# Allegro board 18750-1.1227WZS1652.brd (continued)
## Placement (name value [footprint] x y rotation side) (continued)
C7608  SCD22U10V2KX-1GP  [C402H22]  125.61 142.98 225 bottom
C7610  SC4D7U6D3V2MX-1-GP  [C402H22]  132.44 151.11 45 bottom
C7611  SC4D7U6D3V3KX-GP  [C603H36]  121.02 142.13 180 bottom
C7612  SC1U6D3V1MX-GP  [C0201H14]  134.99 150.82 315 bottom
C7613  SC4D7U6D3V3KX-GP  [C603H36]  118.64 142.16 180 bottom
C7614  SC1U6D3V1MX-GP  [C0201H14]  127.43 147.75 270 top
C7615  SC4D7U6D3V3KX-DLGP  [C603H36]  124.15 131.22 315 top
C7616  SCD1U25V2KX-GP  [C402H22]  127.16 132.91 225 top
C7620  SC4D7U6D3V3KX-GP  [C603H36]  129.49 148.77 45 bottom
C7621  SC4D7U6D3V3KX-GP  [C603H36]  127.94 148.62 270 top
C7622  SC1U6D3V1MX-GP  [C0201H14]  129.72 150.32 315 bottom
C7623  SC10U6D3V3MX-GP  [C603H38]  122.24 144.17 0 bottom
C7624  SC4D7U6D3V3KX-DLGP  [C603H36]  123.32 132.05 315 top
C7625  SC10U6D3V3MX-GP  [C603H38]  131.45 150.72 45 bottom
C7626  SC22U6D3V3MX-1-GP  [C603H40]  119.83 142.13 180 bottom
C7627  SC10U6D3V3MX-GP  [C603H38]  130.2 150.39 180 top
C7628  SC22U6D3V3MX-1-GP  [C603H40]  129.04 150.39 180 top
C7629  SC10U6D3V3MX-GP  [C603H38]  130.12 135.75 135 top
C7630  SC1U6D3V1MX-GP  [C0201H14]  130.1 149.94 315 bottom
C7631  SC1U6D3V1MX-GP  [C0201H14]  130.48 149.56 315 bottom
C7632  SCD1U16V2KX-3GP  [C402H22]  129.14 137.45 315 top
C7633  SC1U6D3V1MX-GP  [C0201H14]  132.21 150.47 180 top
C7634  SC4D7U6D3V3KX-DLGP  [C603H36]  131.37 150.5 180 top
C7744  SC10U6D3V3MX-DL-GP  [C603H36]  143.71 102.88 270 top
C7745  SC10U6D3V3MX-DL-GP  [C603H36]  127.54 118.92 135 bottom
C7746  SC10U6D3V3MX-DL-GP  [C603H36]  126.7 119.76 135 bottom
C7801  SCD1U16V2KX-3GP  [C402H22]  136.99 128.28 225 top
C7802  SCD1U16V2KX-3GP  [C402H22]  138.71 130.02 225 top
C7805  SCD1U16V2KX-3GP  [C402H22]  136.42 132.14 315 top
C7807  SC1U6D3V1MX-GP  [C0201H14]  166.88 130.1 180 top
C7808  SCD1U16V2KX-3GP  [C402H22]  136.18 132.99 315 top
C7809  SCD1U16V2KX-3GP  [C402H22]  137.54 128.84 225 top
C7810  SC1U50V3KX-GP  [C603H32]  127.38 146.91 315 bottom
C7811  SC1U50V3KX-GP  [C603H32]  128.22 146.08 315 bottom
C7812  SC1U50V3KX-GP  [C603H32]  164.8 142.83 270 top
C7813  SC4D7U6D3V3KX-GP  [C603H36]  127.38 143.56 135 bottom
C7814  SC4D7U6D3V3KX-GP  [C603H36]  129.06 145.24 315 bottom
C7817  SC10U6D3V3MX-DL-GP  [C603H36]  126.55 144.4 135 bottom
C7818  SC22U6D3V3MX-1-GP  [C603H40]  134.03 133.15 315 top
C7819  SC10U6D3V3MX-GP  [C603H38]  152.4 149.15 0 top
C7820  SC22U6D3V3MX-1-GP  [C603H40]  155.4 151.74 180 top
C7821  SC22U6D3V3MX-1-GP  [C603H40]  156.72 151.74 180 top
C7822  SC22U6D3V3MX-1-GP  [C603H40]  160.53 151.69 180 top
C7823  SC10U6D3V3MX-GP  [C603H38]  163.2 115.11 0 top
C7824  SC10U6D3V3MX-GP  [C603H38]  154.08 151.74 180 top
C7825  SC1U50V3KX-GP  [C603H32]  164.47 115.11 0 top
C7826  SC1U50V3KX-GP  [C603H32]  165.23 136.7 0 top
C7827  SC1U50V3KX-GP  [C603H32]  154.05 115.11 0 top
C7828  SC1U50V3KX-GP  [C603H32]  156.85 115.11 0 top
C7829  SC10U6D3V3MX-GP  [C603H38]  165.79 130.05 180 top
C7902  SCD1U16V2KX-3GP  [C402H22]  129.64 126.72 315 top
C7905  SCD1U16V2KX-3GP  [C402H22]  132.96 123.97 45 top
C7906  SCD1U16V2KX-3GP  [C402H22]  133.51 124.51 45 top
C7907  SC18P50V2JN-1-GP  [C402H22]  154.34 111.34 180 bottom
C7908  SC18P50V2JN-1-GP  [C402H22]  155.28 108.9 0 bottom
C7934  SC4D7U6D3V3KX-GP  [C603H36]  132.06 127.05 135 top
C7935  SC22U6D3V3MX-1-GP  [C603H40]  131.22 127.89 135 top
C8001  SC4D7U6D3V3KX-GP  [C603H36]  152.79 103.16 90 top
C8002  SC4D7U6D3V3KX-GP  [C603H36]  132.34 131.47 135 top
C8003  SC4D7U6D3V3KX-GP  [C603H36]  164.7 111.71 270 bottom
C8004  SC4D7U6D3V3KX-GP  [C603H36]  150.26 118.15 180 bottom
C8008  SC4D7U6D3V3KX-GP  [C603H36]  127.63 129.62 315 top
C8009  SC4D7U6D3V3KX-GP  [C603H36]  134.7 131.14 315 top
C8010  SC22U6D3V3MX-1-GP  [C603H40]  149.36 111.61 90 top
C8011  SC1U6D3V1MX-GP  [C0201H14]  152.91 105.34 90 top
C8012  SC1U6D3V1MX-GP  [C0201H14]  129.16 133.27 315 top
C8013  SC1U6D3V1MX-GP  [C0201H14]  128.04 132.31 135 top
C8014  SC1U6D3V1MX-GP  [C0201H14]  130.22 134.33 135 top
C8015  SC4D7U6D3V3KX-GP  [C603H36]  132.9 129.57 135 top
C8016  SC4D7U6D3V3KX-GP  [C603H36]  131.02 132.99 315 top
C8017  SC22U6D3V3MX-1-GP  [C603H40]  136.95 130.53 135 top
C8018  SC1U6D3V1MX-GP  [C0201H14]  127.31 131.57 315 top
C8019  SC4D7U6D3V3KX-GP  [C603H36]  143.74 106.99 90 bottom
C8020  SC4D7U6D3V3KX-GP  [C603H36]  150.39 108.23 135 top
C8021  SC4D7U6D3V3KX-GP  [C603H36]  129.31 131.29 135 top
C8022  SC4D7U6D3V3KX-GP  [C603H36]  120.85 125.64 135 bottom
C8023  SC4D7U6D3V3KX-GP  [C603H36]  121.68 124.8 135 bottom
C8024  SC4D7U6D3V3KX-GP  [C603H36]  123.35 123.12 135 bottom
C8025  SC4D7U6D3V3KX-GP  [C603H36]  135.26 128.84 315 top
C8026  SC4D7U6D3V3KX-GP  [C603H36]  130.63 129.8 315 top
C8028  SC1U6D3V1MX-GP  [C0201H14]  135.56 124.28 45 top
C8029  SCD1U16V2KX-3GP  [C402H22]  134.14 123.55 315 top
C8030  SC4D7U6D3V3KX-GP  [C603H36]  122.53 123.98 135 bottom
C8031  SC4D7U6D3V3KX-GP  [C603H36]  152.8 104.35 90 top
C8032  SC4D7U6D3V3KX-GP  [C603H36]  143.71 105.42 270 top
C8034  SCD1U16V2KX-3GP  [C402H22]  162.36 111.94 0 bottom
C8035  SCD1U16V2KX-3GP  [C402H22]  148.92 117.35 270 bottom
C8036  SC1U6D3V1MX-GP  [C0201H14]  136.53 125.15 45 top
C8038  SC10U6D3V3MX-DL-GP  [C603H36]  125.02 121.44 135 bottom
C8039  SC10U6D3V3MX-DL-GP  [C603H36]  124.18 122.28 135 bottom
C8040  SC10U6D3V3MX-DL-GP  [C603H36]  143.71 104.15 270 top
C8041  SC10U6D3V3MX-DL-GP  [C603H36]  119.16 127.3 135 bottom
C8042  SC10U6D3V3MX-DL-GP  [C603H36]  125.86 120.6 135 bottom
C8043  SC10U6D3V3MX-DL-GP  [C603H36]  120.01 126.46 135 bottom
C8047  SC22U6D3V3MX-1-GP  [C603H40]  135.87 126.93 225 top
C8048  SC4D7U6D3V3KX-GP  [C603H36]  138.97 121.51 0 top
C8049  SCD1U16V2KX-3GP  [C402H22]  136.05 124.72 45 top
C8050  SC1U6D3V1MX-GP  [C0201H14]  134.95 125.1 315 top
C8051  SCD1U16V2KX-3GP  [C402H22]  136.88 127.31 225 top
C8101  SC1U6D3V1MX-GP  [C0201H14]  166.75 150.8 270 bottom
C8102  SC1U6D3V1MX-GP  [C0201H14]  158.45 115.09 180 bottom
C8103  SC1U6D3V1MX-GP  [C0201H14]  157.36 129.34 90 bottom
C8104  SC1U6D3V1MX-GP  [C0201H14]  166.5 129.29 270 bottom
C8105  SC1U6D3V1MX-GP  [C0201H14]  166.37 115.88 270 bottom
C8106  SC1U6D3V1MX-GP  [C0201H14]  164.85 136.58 270 bottom
C8107  SC1U6D3V1MX-GP  [C0201H14]  154.31 150.8 90 bottom
C8108  SC1U6D3V1MX-GP  [C0201H14]  157.08 115.88 90 bottom
C8109  SC1U6D3V1MX-GP  [C0201H14]  154.31 137.34 270 top
C8110  SC1U6D3V1MX-GP  [C0201H14]  163.07 129.34 270 bottom
C8111  SC10U6D3V3MX-GP  [C603H38]  158.12 115.11 0 top
C8112  SC10U6D3V3MX-GP  [C603H38]  152.45 118.06 180 top
C8113  SC10U6D3V3MX-GP  [C603H38]  152.83 151.74 180 top
C8114  SC10U6D3V3MX-GP  [C603H38]  163.3 121.97 270 top
C8115  SC1U6D3V1MX-GP  [C0201H14]  155.83 129.34 90 bottom
C8116  SC1U6D3V1MX-GP  [C0201H14]  165.1 150.8 270 bottom
C8117  SC1U6D3V1MX-GP  [C0201H14]  164.72 129.34 270 bottom
C8118  SC1U6D3V1MX-GP  [C0201H14]  157.69 151.03 90 bottom
C8119  SC1U6D3V1MX-GP  [C0201H14]  154.18 129.34 90 bottom
C8120  SC1U6D3V1MX-GP  [C0201H14]  163.2 136.58 270 bottom
C8121  SC1U6D3V1MX-GP  [C0201H14]  155.83 137.34 270 top
C8122  SC1U6D3V1MX-GP  [C0201H14]  166.63 136.58 270 bottom
C8123  SC10U6D3V3MX-GP  [C603H38]  164.57 145.39 270 top
C8124  SC10U6D3V3MX-GP  [C603H38]  163.3 123.14 270 top
C8125  SC10U6D3V3MX-GP  [C603H38]  157.99 151.69 180 top
C8126  SC10U6D3V3MX-GP  [C603H38]  163.96 136.7 0 top
C8127  SC10U6D3V3MX-GP  [C603H38]  160.66 115.11 0 top
C8128  SC10U6D3V3MX-GP  [C603H38]  155.32 115.11 0 top
C8129  SC10U6D3V3MX-GP  [C603H38]  159.39 115.11 0 top
C8130  SC10U6D3V3MX-GP  [C603H38]  164.6 130.05 180 top
C8131  SC1U6D3V1MX-GP  [C0201H14]  155.58 115.88 90 bottom
C8132  SC1U6D3V1MX-GP  [C0201H14]  154.05 115.88 90 bottom
C8136  SC820P50V2KX-1-DL-GP  [C402H22]  164.17 115.12 180 bottom
C8140  SC820P50V2KX-1-DL-GP  [C402H22]  160.81 151.59 270 bottom
C8141  SCD01U50V2KX-1DLGP  [C402H22]  150.12 143.56 90 bottom
C8142  SCD01U50V2KX-1DLGP  [C402H22]  152.28 119.69 270 top
C8143  SC22U6D3V3MX-1-DL-GP  [C603H40]  161.93 115.11 0 top
C8144  SC22U6D3V3MX-1-DL-GP  [C603H40]  165.74 115.11 0 top
C8145  SC22U6D3V3MX-1-DL-GP  [C603H40]  159.26 151.69 180 top
C8146  SC22U6D3V3MX-1-DL-GP  [C603H40]  163.4 130.05 180 top
C8501  SE33U25VM-11-GP  [CT7343H83]  136.15 84.38 180 bottom
C8502  ST22U25VBM-GP  [CT3528H79]  154.64 80.62 90 bottom
C8601  SC1U6D3V1MX-GP  [C0201H14]  167.21 111.46 0 bottom
C8603  SCD1U25V2KX-1-DL-GP  [C402H22]  163.12 111.94 0 bottom
C8605  SC470P50V2KX-3DLGP  [C402H22]  161.19 109.68 90 bottom
C8608  SC470P50V2KX-3DLGP  [C402H22]  161.19 110.49 90 bottom
C8625  SC10U6D3V3MX-GP  [C603H38]  162.92 107.44 180 bottom
C8626  SC10U6D3V3MX-GP  [C603H38]  161.72 107.01 180 bottom
C8627  SC1U6D3V1MX-GP  [C0201H14]  166.55 111.46 0 bottom
C8802  SCD1U16V2KX-L-GP  [C402H22]  97.49 149.86 180 top
C8803  SCD022U16V2KX-3GP  [C402H22]  109.58 150.8 0 top
C8804  SCD01U50V2KX-L-GP  [C402H22]  102.7 142.8 0 bottom
C8805  SCD1U16V2KX-L-GP  [C402H22]  94.03 145.29 270 top
C8806  SCD1U16V2KX-L-GP  [C402H22]  92.03 151.59 90 bottom
C8807  SCD1U16V2KX-L-GP  [C402H22]  101.55 142.01 0 top
C8808  SCD1U16V2KX-L-GP  [C402H22]  108.33 143.69 90 top
C8809  SCD1U16V2KX-L-GP  [C402H22]  100.89 147.06 90 top
C9104  SCD1U16V2KX-3DLGP  [C402H22]  159.54 81.87 0 top
C9106  SC10U6D3V3MX-DL-GP  [C603H36]  164.6 82.86 90 bottom
C9108  SCD1U16V2KX-3DLGP  [C402H22]  164.34 81.46 90 bottom
C9109  SC4D7U6D3V3KX-DLGP  [C603H36]  162.56 79.2 0 bottom
C9112  SCD1U16V2KX-3DLGP  [C402H22]  164.34 78.79 0 bottom
C9113  SCD1U16V2KX-3DLGP  [C402H22]  163.58 78.79 0 bottom
C9201  SC1U6D3V1MX-GP  [C0201H14]  222.56 65.58 180 top
C9202  SC1U6D3V1MX-GP  [C0201H14]  223.07 65.58 180 top
C9203  SCD1U16V2KX-3DLGP  [C402H22]  163.2 68.96 270 top
CPU1  WHISKEY-LAKE-GP  [BGA1528M2446-1H52]  91.24 95.17 270 bottom
D1701  RB520S30-GP  [SOD523AKH26]  146.06 67.37 180 top
D1702  BAW56-9-GP-U  [SOT23-2D4-312H44]  50.93 84.41 180 bottom
D2401  BAT54C-12-GP  [SOT-23-9H44]  21.69 41.23 180 bottom
D2402  L1SS355T1G-GP  [SOD323AKH44]  131.88 39.57 90 bottom
D2403  RB551V30-GP  [SOD323AKH38]  27.59 55.14 0 top
D2404  BAW56-9-GP-U  [SOT23-2D4-312H44]  50.93 81.48 180 bottom
D2501  BAT54C-12-GP  [SOT-23-9H44]  159.47 91.36 180 top
D2502  RB551V30-GP  [SOD323AKH38]  164.97 89.71 0 top
D2503  BAT54A-11-GP  [SOT-23-9H44]  157.94 92 180 bottom
D2601  RB551V30-GP  [SOD323AKH38]  162.87 85.7 90 top
D2703  BAT54C-12-GP  [SOT-23-9H44]  22.89 21.85 180 top
D2901  BAT54A-11-GP  [SOT-23-9H44]  24.77 6.66 0 top
D4001  L1SS355T1G-GP  [SOD323AKH44]  146.71 74.12 270 top
D4002  RB551V30-GP  [SOD323AKH38]  83.3 40.23 90 bottom
D4003  RB551V30-GP  [SOD323AKH38]  86.58 40.23 270 bottom
D4301  P6AF24A-R1-00001-GP  [D4724AKH44]  23.37 121.62 270 top
D4302  LBAV99LT1G-1-GP  [SOT23-2D4-312H44]  25.25 92.41 90 top
D4304  SMF18A-GP  [SOD123AK-2H43]  150.83 38.89 180 bottom
D4305  RB551V30-GP  [SOD323AKH38]  35.56 133.33 90 top
D5502  BAT54C-12-GP  [SOT-23-9H44]  157.23 79.43 0 top
D5503  BAT54C-12-GP  [SOT-23-9H44]  210.49 47.78 180 bottom
D5504  RB751S40T1G-GP  [D1608AK-UH28]  136.45 79.68 90 bottom
D5505  RB751S40T1G-GP  [D1608AK-UH28]  222.25 69.01 270 top
D5701  BAW56-9-GP-U  [SOT23-2D4-312H44]  18.7 90.96 0 top
D6401  BAT54A-11-GP  [SOT-23-9H44]  33.66 20.12 180 top
D6403  RB751VM-40TE-17-GP  [SOD323-2513AKH36]  50.8 64.9 0 top
D7201  SBA0520Q-R1-00001-GP-U  [D1006-0305AK-UH22]  53.32 127.76 0 top
D7202  SBA0520Q-R1-00001-GP-U  [D1006-0305AK-UH22]  54.68 127.2 270 top
D7401  SS3040HE-GP  [SOD123AK-3718-1H40]  41.13 125.83 270 top
D7902  L1SS355T1G-GP  [SOD323AKH44]  150.4 112.14 180 bottom
D8801  L1SS355T1G-GP  [SOD323AKH44]  99.34 143.21 270 bottom
D8803  L1SS355T1G-GP  [SOD323AKH44]  99.34 145.01 90 bottom
DBEC1  ACES-CON6-58-GP  [50696-00601-001]  46.54 74.58 90 top
DBG1  ACES-CON14-5-GP  [87212-1400N]  35.11 49.15 180 top
DCIN1  ACES-CON8-13-GP-U2  [50224-0080N-W02-U]  20.7 128.8 0 bottom
DM1  DDR4-260P-78-GP-U  [ADDR0206-P013A-1-U]  63.7 47 0 bottom
DM2  DDR4-260P-78-GP-U  [ADDR0206-P013A-1-U]  139.9 47 0 bottom
EC1202  SC2D2U6D3V2MX-DL-GP  [C402H22]  109.43 44.58 180 top
EC1203  SCD1U25V2KX-GP  [C402H22]  146.05 45.65 180 top
EC1303  SC2D2U6D3V2MX-DL-GP  [C402H22]  118.57 45.92 180 top
EC1707  SCD1U16V2KX-3DLGP  [C402H22]  157.13 74.56 180 top
EC1712  SCD1U16V2KX-3DLGP  [C402H22]  156.03 70.01 0 top
EC1801  SC10P50V2JN-4DLGP  [C402H22]  39.86 53.42 0 top
EC1803  SC4D7P50V2BN-2-GP  [C402H22]  102.62 76.56 90 top
EC1901  SC10P50V2JN-4DLGP  [C402H22]  26.19 21.02 90 top
EC1903  SC33P50V2JN-3DLGP  [C402H22]  27.87 20.73 90 top
EC2002  SC1KP50V2KX-1DLGP  [C402H22]  139.63 95.52 180 bottom
EC2201  SCD1U25V2KX-1-DL-GP  [C402H22]  100.69 98.07 270 top
EC2501  SC4D7P50V2BN-2-GP  [C402H22]  132.69 78.87 180 bottom
EC2502  SC4D7P50V2BN-2-GP  [C402H22]  129.31 89.84 90 bottom
EC2503  SC10P50V2JN-4DLGP  [C402H22]  131.93 78.87 180 bottom
EC2504  SC10P50V2JN-4DLGP  [C402H22]  135.64 89.71 90 top
EC2505  SC4D7P50V2BN-2-GP  [C402H22]  137.76 89.37 270 top
EC2506  SC4D7P50V2BN-2-GP  [C402H22]  134.85 80.11 90 top
EC2601  SC10P50V2JN-4DLGP  [C402H22]  30.15 56.97 270 top
EC2602  SC10P50V2JN-4DLGP  [C402H22]  27.44 52.76 0 top
EC2701  SC1KP16V2KX-DL-GP  [C402H22]  30.56 4.6 0 top
EC2702  SC1KP16V2KX-DL-GP  [C402H22]  22.94 4.22 0 top
EC2703  SC1KP16V2KX-DL-GP  [C402H22]  34.59 5.27 45 top
EC2704  SC1KP16V2KX-DL-GP  [C402H22]  20.78 20.35 180 top
EC2705  SC1KP16V2KX-DL-GP  [C402H22]  20.02 20.35 180 top
EC2706  SC22P50V2JN-4GP  [C402H22]  25.05 21.87 0 top
EC2707  SC22P50V2JN-4GP  [C402H22]  28.55 17.96 180 top
EC2708  SC22P50V2JN-4GP  [C402H22]  29.31 17.96 180 top
EC2901  SC1KP50V2KX-1DLGP  [C402H22]  19.51 2.82 0 top
EC2902  SC1KP50V2KX-1DLGP  [C402H22]  18.67 2.06 180 top
EC2903  SC1KP50V2KX-1DLGP  [C402H22]  18.34 5.08 0 top
EC2904  SC1KP50V2KX-1DLGP  [C402H22]  19.1 4.32 180 top
EC2905  SC1KP16V2KX-DL-GP  [C402H22]  17.38 11.81 90 top
EC2906  SC1KP16V2KX-DL-GP  [C402H22]  18.34 17.6 90 top
EC2907  SC680P50V2KX-2DLGP  [C402H22]  20.07 10.21 270 top
EC2908  SC680P50V2KX-2DLGP  [C402H22]  17.91 9.83 0 top
EC3513  SC1KP16V2KX-DL-GP  [C402H22]  18.11 56.87 180 bottom
EC4301  SC10U25V5KX-DL-GP  [C805H58]  17.06 126.64 270 top
EC4302  SC1KP50V2KX-1DLGP  [C402H22]  20.72 126.88 270 top
EC4306  SC10P50V2JN-4GP  [C402H22]  134.24 35.49 90 top
EC4307  SC1KP50V2KX-1DLGP  [C402H22]  144.58 40.87 270 bottom
EC4308  SC1KP50V2KX-1DLGP  [C402H22]  142.12 40.62 90 bottom
EC4309  SC10P50V2JN-4GP  [C402H22]  134.24 37.01 270 top
EC4310  SC10P50V2JN-4GP  [C402H22]  134.24 36.25 270 top
EC4311  SCD1U25V2KX-GP  [C402H22]  17.91 123.62 270 top
EC4312  SC1KP50V2KX-1DLGP  [C402H22]  20.7 128.48 270 top
EC4313  SC1KP50V2KX-1DLGP  [C402H22]  20.7 127.71 270 top
EC4534  SCD1U25V2KX-GP  [C402H22]  51.31 32.06 0 bottom
EC4701  SC1KP16V2KX-DL-GP  [C402H22]  71.38 102.41 180 top
EC5001  SC1KP16V2KX-DL-GP  [C402H22]  90.3 121.08 270 top
EC5503  SC33P50V2JN-3DLGP  [C402H22]  213.23 43.67 45 top
EC5504  SC33P50V2JN-3DLGP  [C402H22]  215.36 45.26 180 top
EC6401  SCD1U16V2KX-3GP  [C402H22]  211.71 55.55 270 top
EC6402  SCD1U25V2KX-1-DL-GP  [C402H22]  10.67 129.59 0 bottom
EC6403  SC1KP50V2KX-1DLGP  [C402H22]  210.19 55.55 90 top
EC6404  SCD1U25V2KX-1-DL-GP  [C402H22]  13.77 129.62 0 bottom
EC6405  SCD1U25V2KX-1-DL-GP  [C402H22]  201.67 56.09 180 bottom
EC6501  SC33P50V2JN-3GP  [C402H22]  108.97 37.14 270 top
EC6502  SC33P50V2JN-3GP  [C402H22]  103.48 31.01 270 top
EC6503  SC33P50V2JN-3GP  [C402H22]  110.49 37.14 90 top
EC6504  SC33P50V2JN-3GP  [C402H22]  106.18 35.82 90 top
EC6601  SC1KP16V2KX-DL-GP  [C402H22]  203.74 37.19 270 top
EC8901  SC1KP16V2KX-DL-GP  [C402H22]  55.32 46.69 180 top
EC8902  SC1KP16V2KX-DL-GP  [C402H22]  61.37 47.3 0 top
EC8903  SC1KP16V2KX-DL-GP  [C402H22]  110.19 44.58 180 top
EC8904  SC1KP16V2KX-DL-GP  [C402H22]  98.96 44.98 270 top
EC8905  SC1KP16V2KX-DL-GP  [C402H22]  68.81 76.68 0 top
EC8906  SC1KP16V2KX-DL-GP  [C402H22]  76.2 76.68 180 top
EC8907  SC1KP16V2KX-DL-GP  [C402H22]  84.61 76.51 180 top
EC8908  SC1KP16V2KX-DL-GP  [C402H22]  168.43 50.32 90 top
EC8909  SC1KP16V2KX-DL-GP  [C402H22]  92.15 75.67 180 top
EC8910  SC1KP16V2KX-DL-GP  [C402H22]  97.29 76.68 180 top
EC8911  SCD1U25V2KX-GP  [C402H22]  92.46 45.44 180 top
EC8912  SCD1U25V2KX-GP  [C402H22]  119.33 45.92 180 top
EC8913  SCD1U25V2KX-GP  [C402H22]  139.17 47.96 0 top
EC8914  SCD1U25V2KX-GP  [C402H22]  158.8 48.82 0 top
EC8915  SCD1U25V2KX-GP  [C402H22]  161.98 46.36 0 top
EC8923  SC1KP50V2KX-1GP  [C402H22]  110.82 123.95 180 top
EC8924  SC1KP50V2KX-1GP  [C402H22]  111.53 146.31 180 top
EC8925  SC1KP50V2KX-1GP  [C402H22]  105.51 139.52 270 top
EC8927  SCD1U25V2KX-GP  [C402H22]  94.36 141.02 270 top
EC8929  SC1KP50V2KX-1GP  [C402H22]  208.41 39.32 90 bottom
EC8930  SCD1U25V2KX-GP  [C402H22]  178.06 63.37 135 top
EC8932  SCD1U25V2KX-GP  [C402H22]  78.31 32.47 0 top
EC8933  SC1U10V2KX-1GP  [C402H22]  64.16 36.53 270 bottom
EC8934  SC1U10V2KX-1GP  [C402H22]  187.97 33.08 180 top
EC8935  SC1U10V2KX-1GP  [C402H22]  80.63 38.59 270 top
EC8936  SCD1U16V2KX-3GP  [C402H22]  204.8 59.73 270 top
EC8937  SC1U10V2KX-1GP  [C402H22]  156.21 36.5 180 top
EC8938  SC1U10V2KX-1GP  [C402H22]  155.45 36.5 180 top
EC8939  SC1U10V2KX-1GP  [C402H22]  64.16 37.29 270 bottom
EC8940  SCD1U16V2KX-3DLGP  [C402H22]  59.54 91.97 270 bottom
EC8941  SCD1U16V2KX-3DLGP  [C402H22]  41.66 68 0 top
EC8942  SCD1U16V2KX-3DLGP  [C402H22]  52.66 130.25 0 bottom
EC8943  SCD1U16V2KX-3DLGP  [C402H22]  47.88 101.32 270 top
EC8944  SCD1U16V2KX-3DLGP  [C402H22]  45.93 63.58 90 top
EC8945  SCD1U16V2KX-3DLGP  [C402H22]  177.04 58.47 90 top
EC8946  SCD1U16V2KX-3DLGP  [C402H22]  203 59.72 90 top
EC8947  SC1U10V2KX-1GP  [C402H22]  16.56 90.76 180 top
EC8948  SC1U10V2KX-1GP  [C402H22]  18.93 98.32 0 top
EC8949  SC1U10V2KX-1GP  [C402H22]  19.76 122.94 270 top
EC8950  SC1U6D3V1MX-GP  [C0201H14]  51.03 95.81 0 bottom
EC8951  SC1U6D3V1MX-GP  [C0201H14]  55.76 119.97 45 bottom
EC8952  SC1U6D3V1MX-GP  [C0201H14]  81.31 31.75 0 bottom
EC8953  SC1U6D3V1MX-GP  [C0201H14]  90.48 30.58 180 top
EC8955  SC1KP50V2KX-1GP  [C402H22]  176.36 65.05 135 top
EC8957  SCD1U25V2KX-GP  [C402H22]  80.57 32.97 270 bottom
EC8959  SC1U6D3V1MX-GP  [C0201H14]  45.72 101.7 0 top
EC8960  SC1U6D3V1MX-GP  [C0201H14]  197.11 34.34 0 top
EC8961  SC1KP16V2KX-DL-GP  [C402H22]  150.88 98.22 90 top
EC8962  SC1KP50V2KX-1GP  [C402H22]  140.74 38.33 270 top
EC8963  SCD1U25V2KX-GP  [C402H22]  196.83 40.9 270 top
EC8964  SCD1U25V2KX-GP  [C402H22]  178.62 62.84 315 top
EC8965  SC1KP16V2KX-DL-GP  [C402H22]  152.91 106.12 90 top
EC8966  SC1KP16V2KX-DL-GP  [C402H22]  138.28 97.95 0 top
EC8967  SC1KP16V2KX-DL-GP  [C402H22]  149.62 110.58 90 top
EC8968  SC1KP16V2KX-DL-GP  [C402H22]  130.05 113.38 315 top
EC8969  SC1KP50V2KX-1DLGP  [C402H22]  29.29 126.08 180 top
EC8971  SC1KP16V2KX-DL-GP  [C402H22]  200 54.43 180 top
EC8972  SC1KP16V2KX-DL-GP  [C402H22]  31.52 110.24 90 top
EC8973  SC1KP16V2KX-DL-GP  [C402H22]  204.47 54.54 90 top
EC8974  SCD1U25V2KX-GP  [C402H22]  199.24 54.43 180 top
EC8975  SC1U6D3V1MX-GP  [C0201H14]  171.99 43.54 90 top
EC8976  SCD1U25V2KX-GP  [C402H22]  204.49 53.72 90 top
EC8977  SC1U6D3V1MX-GP  [C0201H14]  51.54 95.81 0 bottom
EC8978  SC1U6D3V1MX-GP  [C0201H14]  56.14 120.35 45 bottom
EC8979  SC1U6D3V1MX-GP  [C0201H14]  80.8 31.75 0 bottom
EC8980  SC1U6D3V1MX-GP  [C0201H14]  89.97 30.58 180 top
EC8986  SC1U10V2KX-1GP  [C402H22]  194.06 34.34 0 top
EC8987  SC1U10V2KX-1GP  [C402H22]  175.8 37.34 0 top
EC8988  SC1U10V2KX-1GP  [C402H22]  110.37 30.38 180 top
EC8989  SC1U10V2KX-1GP  [C402H22]  96.8 34.06 90 top
EC8990  SC1U10V2KX-1GP  [C402H22]  21.29 24.33 0 top
EC8991  SC1U6D3V1MX-GP  [C0201H14]  147.65 33.38 270 top
EC8992  SC1U6D3V1MX-GP  [C0201H14]  131.6 32.56 45 top
EC8993  SC1U6D3V1MX-GP  [C0201H14]  109.53 29.64 180 top
EC8994  SC1U6D3V1MX-GP  [C0201H14]  54.08 31.12 180 top
EC8995  SC1U6D3V1MX-GP  [C0201H14]  76.36 41.28 180 top
EC8996  SC1U6D3V1MX-GP  [C0201H14]  168.46 40.29 270 top
EC8997  SC1U6D3V1MX-GP  [C0201H14]  132.39 103.3 270 top
EC8998  SC1U6D3V1MX-GP  [C0201H14]  172.47 47.96 90 top
EC8999  SC1U6D3V1MX-GP  [C0201H14]  42.14 30.44 90 bottom
EC9001  SC1U6D3V1MX-GP  [C0201H14]  57.51 37.11 90 top
ED301  AZ5125-02S-R7G-GP  [SOT23-2D4-312H46]  90.15 115.75 180 bottom
ED1217  PESD5V0U2BT-215-GP  [SOT23-2D4-312H44]  56.54 39.68 270 bottom
ED1302  PESD5V0U2BT-215-GP  [SOT23-2D4-312H44]  128.5 39.83 180 bottom
ED1701  PESD5V0S1BB-GP-U  [SOD-523-2H26]  159.49 79.3 180 bottom
ED1702  PESD5V0S1BB-GP-U  [SOD-523-2H26]  23.22 60.64 90 bottom
ED1703  PESD5V0S1BB-GP-U  [SOD-523-2H26]  61.45 137.82 270 bottom
ED1705  PESD5V0S1BB-GP-U  [SOD-523-2H26]  41.83 64.43 270 top
ED1706  PESD5V0S1BB-GP-U  [SOD-523-2H26]  31.55 56.03 180 top
ED1707  PESD5V0S1BB-GP-U  [SOD-523-2H26]  96.38 116.37 90 bottom
ED1801  PESD5V0S1BB-GP-U  [SOD-523-2H26]  166.93 65.18 90 top
ED1802  PESD5V0S1BB-GP-U  [SOD-523-2H26]  167.52 63.27 0 top
ED2403  AZ5125-02S-R7G-GP  [SOT23-2D4-312H46]  93.86 147.74 270 top
ED2910  AZ5125-02S-R7G-GP  [SOT23-2D4-312H46]  21.31 7.47 180 top
ED2911  AZ5125-02S-R7G-GP  [SOT23-2D4-312H46]  17.88 7.48 180 top
ED2912  AZ5125-02S-R7G-GP  [SOT23-2D4-312H46]  17.91 21.39 0 top
ED3201  AZ1043-04F-R7G-GP  [DFN10G2510H22]  40.65 84.41 90 bottom
ED3202  AZ1043-04F-R7G-GP  [DFN10G2510H22]  40.65 84.42 90 top
ED3501  AZ1043-04F-R7G-GP  [DFN10G2510H22]  17.07 53.29 270 bottom
ED3502  AZC099-04S-2-GP  [SOT-6H58]  17.91 47.04 270 bottom
ED3503  AZ1043-04F-R7G-GP  [DFN10G2510H22]  17.3 43.82 270 bottom
ED4303  AZ5725-01FDR7G-GP  [SOD882-10D6-1H20]  17.91 124.51 90 top
ED4304  LBAV99LT1G-1-GP  [SOT23-2D4-312H44]  124.97 37.3 180 bottom
ED4305  LBAV99LT1G-1-GP  [SOT23-2D4-312H44]  128.58 36.53 90 bottom
ED4306  LBAV99LT1G-1-GP  [SOT23-2D4-312H44]  124.97 39.82 180 bottom
ED5502  AZC099-04S-2-GP  [SOT-6H58]  214.18 48.16 270 bottom
ED5701  AZ1043-04F-R7G-GP  [DFN10G2510H22]  16.79 95.66 270 bottom
ED5702  AZ1043-04F-R7G-GP  [DFN10G2510H22]  16.87 98.71 90 bottom
ED5703  AZ1043-04F-R7G-GP  [DFN10G2510H22]  17.07 96.39 90 top
ED6001  AZ1043-04F-R7G-GP  [DFN10G2510H22]  164.21 36.12 0 top
ED6401  AZ5125-02S-R7G-GP  [SOT23-2D4-312H46]  211.48 54.48 0 bottom
ED6601  AZC099-04S-2-GP  [SOT-6H58]  202.5 41.16 90 bottom
ED7301  L05ESDL5V0NA-4-GP  [SLP2510P8-1H22]  11.69 116.18 270 bottom
ED7302  L05ESDL5V0NA-4-GP  [SLP2510P8-1H22]  11.31 127.31 270 bottom
ED7307  AZ5125-02S-R7G-GP  [SOT23-2D4-312H46]  18.09 121.51 270 top
ED7311  TVUFB0201AC0-GP  [SOD882-10D6-UH22]  11.61 122.51 90 bottom
ED7312  TVUFB0201AC0-GP  [SOD882-10D6-UH22]  10.09 122.51 270 bottom
ED7313  TVUFB0201AC0-GP  [SOD882-10D6-UH22]  13.62 121.31 180 bottom
ED7314  TVUFB0201AC0-GP  [SOD882-10D6-UH22]  13.62 119.79 0 bottom
ED7315  AZ5125-02S-R7G-GP  [SOT23-2D4-312H46]  11.94 118.16 180 top
ED9202  AZC099-04S-2-GP  [SOT-6H58]  207.78 55.45 270 bottom
EL3501  COIL-90OHM-100MHZ-5-GP  [L125100-4P-4H24]  18.95 49.79 270 bottom
EL3502  FILTER-4P-98-GP  [L125100-4P-5H24]  19.26 54.05 90 bottom
EL3503  FILTER-4P-98-GP  [L125100-4P-5H24]  19.28 52.5 90 bottom
EL3504  FILTER-4P-98-GP  [L125100-4P-5H24]  19.61 44.58 90 bottom
EL3505  FILTER-4P-98-GP  [L125100-4P-5H24]  19.59 42.98 90 bottom
EL3506  COIL-90OHM-100MHZ-5-GP  [L125100-4P-4H24]  21.82 46.33 180 bottom
EL4301  -  [0R0805-PAD]  24.08 127.46 90 top
EL4302  -  [0R0805-PAD]  24.08 129.26 90 top
EL4303  -  [0R0805-PAD]  17.53 128.96 180 top
EL4304  -  [0R0805-PAD]  17.48 122.56 180 bottom
EL5501  COIL-90OHM-100MHZ-5-GP  [L125100-4P-4H24]  213.16 49.79 180 top
EL5701  FILTER-4P-170-GP  [L125100-4P-3H24]  19.59 94.67 270 bottom
EL5702  FILTER-4P-170-GP  [L125100-4P-3H24]  19.61 96.22 270 bottom
EL5703  FILTER-4P-170-GP  [L125100-4P-3H24]  19.61 97.77 270 bottom
EL5704  FILTER-4P-170-GP  [L125100-4P-3H24]  19.61 99.34 270 bottom
EL6101  COIL-90OHM-100MHZ-5-GP  [L125100-4P-4H24]  31.78 97.64 0 top
EL6601  FILTER-4P-137-GP-U  [L125100-4P-4H28]  205.4 39.75 180 bottom
EL6602  FILTER-4P-137-GP-U  [L125100-4P-4H28]  205.41 41.31 180 bottom
EL7105  COIL-90OHM-100MHZ-5-GP  [L125100-4P-4H24]  28.58 117.81 180 top
EL7106  COIL-90OHM-100MHZ-5-GP  [L125100-4P-4H24]  36.22 116.89 270 top
ER2701  0R2J-2-GP  [R402H16]  26.85 19.25 0 top
ER5701  150R2F-1-GP  [R402H16]  15.05 94.72 0 bottom
ER5702  150R2F-1-GP  [R402H16]  15.05 96.42 0 bottom
ER5703  150R2F-1-GP  [R402H16]  15.05 98.12 0 bottom
ER5704  150R2F-1-GP  [R402H16]  15.05 99.82 0 bottom
F5503  POLYSW-1D1A24V-GP-U  [POLYSW-4633-UH43]  211.98 41.2 90 bottom
F5504  POLYSW-1D1A6V-9-GP-U  [POLYSW-2114H30]  157.36 99.24 180 bottom
F5505  POLYSW-1D1A6V-9-GP-U  [POLYSW-2114H30]  159.62 108.51 180 top
F5506  POLYSW-1D1A6V-9-GP-U  [POLYSW-2114H30]  224.39 40.87 270 top
F5701  POLYSW-1D1A6V-9-GP-U  [POLYSW-2114H30]  17.1 100.26 180 top
F6501  POLYSW-1D1A6V-9-GP-U  [POLYSW-2114H30]  80.83 36.6 180 bottom
FAN1  ACES-CON4-29-GP  [50224-0040N-001]  162.7 87.2 270 bottom
FC1102  SC2D2U6D3V2MX-DL-GP  [C402H22]  110.57 47.68 180 top
FC1103  SC2D2U6D3V2MX-DL-GP  [C402H22]  134.75 49.2 0 top
FC8901  SCD1U25V2KX-GP  [C402H22]  147.65 34.18 270 top
FC8902  SCD1U25V2KX-GP  [C402H22]  195.33 64.29 270 top
FC8903  SC1U10V2KX-1GP  [C402H22]  22.23 92.31 90 top
FC8904  SC1U6D3V1MX-GP  [C0201H14]  72.27 92.57 0 top
FC8905  SC1U6D3V1MX-GP  [C0201H14]  68.47 104.39 0 top
FC8906  SC1U6D3V1MX-GP  [C0201H14]  74.43 101.4 0 top
FC8907  SCD1U25V2KX-GP  [C402H22]  54.88 31.11 180 top
FC8908  SCD1U25V2KX-GP  [C402H22]  103 96.59 270 top
FC8909  SCD1U25V2KX-GP  [C402H22]  17.25 37.19 270 bottom
FC8910  SCD1U25V2KX-GP  [C402H22]  18.85 46.74 90 top
FC8911  SCD1U25V2KX-GP  [C402H22]  55.73 134.09 0 top
FC8912  SC68P50V2JN-1DLGP  [C402H22]  154.69 36.5 180 top
FC8913  SC68P50V2JN-1DLGP  [C402H22]  60.48 36.22 270 top
FC8914  SC68P50V2JN-1DLGP  [C402H22]  183.41 33.08 180 top
FC8915  SC68P50V2JN-1DLGP  [C402H22]  166.8 86.23 180 top
FC8916  SC68P50V2JN-1DLGP  [C402H22]  80.64 37.8 270 top
FC8917  SCD1U25V2KX-GP  [C402H22]  19.74 120.65 270 top
FC8918  SCD1U16V2KX-3GP  [C402H22]  160 108.03 180 bottom
FC8919  SCD1U16V2KX-3GP  [C402H22]  215.6 43.82 180 bottom
FC8921  SC68P50V2JN-1DLGP  [C402H22]  36.07 34.8 90 bottom
FC8922  SCD1U25V2KX-GP  [C402H22]  97.72 141.56 270 bottom
FC8923  SC68P50V2JN-1DLGP  [C402H22]  97.72 140.79 270 bottom
FC8924  SC68P50V2JN-1DLGP  [C402H22]  158.14 83.75 270 bottom
FC8929  SC68P50V2JN-1DLGP  [C402H22]  76.74 32.46 0 top
FC8930  SC68P50V2JN-1DLGP  [C402H22]  77.52 32.46 0 top
FC8931  SCD1U25V2KX-GP  [C402H22]  94.36 143.31 270 top
FC8932  SCD1U25V2KX-GP  [C402H22]  94.36 142.55 270 top
FC8933  SCD1U25V2KX-GP  [C402H22]  178.36 35.46 270 top
FC8934  SCD1U25V2KX-GP  [C402H22]  94.36 141.78 270 top
FC8935  SCD1U25V2KX-GP  [C402H22]  156.95 88.8 180 top
FC8936  SCD1U25V2KX-GP  [C402H22]  158.14 84.51 270 bottom
FC8937  SCD1U25V2KX-GP  [C402H22]  175.82 65.61 135 top
FC8938  SCD1U25V2KX-GP  [C402H22]  136.6 99.16 0 top
FC8939  SCD1U25V2KX-GP  [C402H22]  125.43 38.18 180 top
FC8940  SCD1U25V2KX-GP  [C402H22]  155.3 78.59 90 bottom
FC8941  SCD1U25V2KX-GP  [C402H22]  53.06 132.26 180 bottom
FC8942  SCD1U25V2KX-GP  [C402H22]  75.82 142.24 270 bottom
FC8944  SCD1U25V2KX-GP  [C402H22]  124.64 38.18 180 top
FC8945  SCD1U25V2KX-GP  [C402H22]  59.41 137.95 180 bottom
FC8946  SCD1U25V2KX-GP  [C402H22]  64.14 139.83 180 top
FC8947  SCD1U25V2KX-GP  [C402H22]  112.32 146.31 180 top
FC8948  SCD1U25V2KX-GP  [C402H22]  72.95 141.05 270 top
FC8951  SCD1U25V2KX-GP  [C402H22]  110.06 123.95 180 top
FC8952  SCD1U25V2KX-GP  [C402H22]  128.27 109.4 135 top
FC8953  SCD1U25V2KX-GP  [C402H22]  176.94 64.49 135 top
FC8954  SCD1U25V2KX-GP  [C402H22]  177.5 63.93 135 top
FC8955  SCD1U25V2KX-GP  [C402H22]  210.24 40.01 270 top
FC8956  SCD1U25V2KX-GP  [C402H22]  126.22 38.18 180 top
FC8957  SCD1U25V2KX-GP  [C402H22]  140.74 39.12 270 top
FC8958  SCD1U25V2KX-GP  [C402H22]  80.57 33.73 270 bottom
FC8959  SCD1U25V2KX-GP  [C402H22]  158.14 82.98 270 bottom
FC8960  SCD1U25V2KX-GP  [C402H22]  208.44 40.11 90 bottom
FC8961  SC1U10V2KX-1GP  [C402H22]  154.41 104.3 90 bottom
FC8962  SCD1U25V2KX-GP  [C402H22]  40.43 30.43 0 bottom
FC8963  SC1500P50V2KX-2-DL-GP  [C402H22]  215.38 37.87 0 top
FC8964  SC1500P50V2KX-2-DL-GP  [C402H22]  216.51 40.67 180 top
FC8965  SCD1U25V2KX-GP  [C402H22]  64.9 139.83 180 top
FC8966  SCD1U25V2KX-GP  [C402H22]  164.42 80.42 90 bottom
FC8967  SCD1U25V2KX-GP  [C402H22]  76.18 37.8 270 bottom
FC8970  SCD1U25V2KX-GP  [C402H22]  173.1 51.54 0 top
FC8981  SCD1U25V2KX-GP  [C402H22]  79.63 114.89 180 bottom
FC8983  SCD1U25V2KX-GP  [C402H22]  65.74 100.66 270 top
FC8984  SCD1U25V2KX-GP  [C402H22]  128.58 102.87 270 bottom
FC8985  SCD1U25V2KX-GP  [C402H22]  83.42 91.16 270 top
FC8986  SCD1U25V2KX-GP  [C402H22]  27.44 101.96 90 top
FC8987  SCD1U25V2KX-GP  [C402H22]  143.64 106.4 270 top
FC8988  SCD1U25V2KX-GP  [C402H22]  151.1 107.55 135 top
FC8990  SCD1U25V2KX-GP  [C402H22]  68.48 100.13 0 top
FC8991  SCD1U25V2KX-GP  [C402H22]  73.97 92.53 0 top
FC8992  SCD1U25V2KX-GP  [C402H22]  97.39 90.83 180 top
FC8993  SCD1U25V2KX-GP  [C402H22]  99.63 96.28 90 top
FC8994  SCD1U25V2KX-GP  [C402H22]  162.55 50.8 0 top
FC8995  SCD1U25V2KX-GP  [C402H22]  139.51 39.44 0 top
FC8996  SCD1U25V2KX-GP  [C402H22]  109.84 42.39 0 top
FC8997  SCD1U25V2KX-GP  [C402H22]  69.2 42.54 0 top
FC8998  SCD1U25V2KX-GP  [C402H22]  196.35 34.34 0 top
FC8999  SCD1U25V2KX-GP  [C402H22]  128.63 107.05 270 bottom
FC9001  SCD1U25V2KX-GP  [C402H22]  197.97 58.19 90 top
FC9002  SC1U10V2KX-1GP  [C402H22]  156.59 38.28 270 top
FC9003  SC1U10V2KX-1GP  [C402H22]  184.98 33.86 0 top
FC9004  SC1U10V2KX-1GP  [C402H22]  184.2 33.86 0 top
FC9005  SC1U6D3V1MX-GP  [C0201H14]  43.08 106.48 180 top
FC9006  SC1U6D3V1MX-GP  [C0201H14]  32.06 105.28 180 top
FP1  PTWO-CON8-11-GP  [FH52-8S-D5SH]  221.7 65.8 0 bottom
G1801  GAP-OPEN  [CON2O-U]  169.01 65.71 270 top
G6401  GAP-OPEN  [CON2O-U]  224.97 62.03 270 bottom
G6402  GAP-OPEN  [CON2O-U]  208.79 59.11 270 top
GPU1  N17S-G1-A1-GP  [BGA595M23H83]  133.57 131.98 45 bottom
H1  HOLE233R142-GP-U1  [HOLE233R142]  59.01 108.27 180 bottom
H2  HOLE233R142-GP-U1  [HOLE233R142]  59.01 83.97 180 bottom
H3  HOLE233R142-GP-U1  [HOLE233R142]  120.01 83.97 180 bottom
H4  HOLE233R142-GP-U1  [HOLE233R142]  120.01 108.27 180 bottom
H5  HOLE233R142-GP-U1  [HOLE233R142]  112.87 134.04 180 bottom
H6  HOLE233R142-GP-U1  [HOLE233R142]  145.65 148.93 180 bottom
H7  HOLE233R142-GP-U1  [HOLE233R142]  142.14 113.1 180 bottom
H9  HOLE335R178-GP  [HOLE335R178]  185.8 65.8 180 bottom
H10  HOLE335R178-GP  [HOLE335R178]  125.7 30.4 180 bottom
H11  HOLE256R115-GP  [HOLE256R115]  5.4 43.33 180 bottom
H12  HOLE335R229-GP  [HOLE335R229]  20.7 115.3 180 bottom
H13  HOLE256R115-GP  [HOLE256R115]  63.7 145.8 0 bottom
H14  HOLE256R115-GP  [HOLE256R115]  101.7 151.8 180 bottom
H16  HOLE335R178-GP  [HOLE335R178]  210.95 34.25 180 bottom
H17  HOLE256R115-GP  [HOLE256R115]  7.7 133.8 180 bottom
H18  HOLE256R115-GP  [HOLE256R115]  5.7 113.2 180 bottom
HDA27  ALC3204-CG-GP-U  [QFN40J5-G3D75H36]  26.93 13.77 0 top
HDD1  ACES-CON20-37-GP-U  [50406-02071-W01]  160.9 36.8 0 bottom
HDD2  STM-CON12-1-GP  [FFSKL05007N12C]  162.9 35.55 180 bottom
HDMI1  SKT-HDMI23-157-GP  [SKT-HDMI23-188139-2]  3.5 99.35 90 bottom
HPMIC1  AUDIO-JK677-GP  [14-00790-1A03-A]  3.41 15.2 90 bottom
HS3  STF237R113H86-GP  [STF237R113H86]  40.2 131.05 0 bottom
IOBD1  ACES-CON20-29-GP-U  [51530-02001-W01-U]  198.55 35.45 180 bottom
JUSB1  SKT-USB36-20-GP  [SKT-USB36-124102-1]  2.04 123.7 90 bottom
KB1  ACES-CON30-29-GP  [50699-03001-W01]  65.92 32.2 180 bottom
KBBL1  ACES-CON4-90-GP-U  [50698-00401-W01-U]  86.84 32.1 180 bottom
L7101  MCB1005H470FBP-GP  [L402H24]  17.88 108.36 180 bottom
L7602  MHC1608S121PBP-GP  [L603H38]  133.66 151.31 90 top
L7801  MHC1608S300QBP-GP  [L603H38]  131.8 134.83 225 top
L7901  MHC1608S300QBP-GP  [L603H38]  134.42 125.83 315 top
L7902  MCB1608S181FBP-GP  [L603H38]  132.56 125.8 315 top
LCD1  STAR-CON40-8-GP  [300E40-1010RA-G3]  221.7 47.3 270 bottom
LED1  LED-YW-5-GP  [LED3020-3P-19H44]  2.7 134.8 0 bottom
LED2  LED-Y-102-GP  [LED11516AKH28]  9.7 65.8 0 bottom
MESW1  SW-SLIDE3P-11-GP  [MSS3-Q-T-R]  13.15 43.33 270 bottom
NOREF  -  []  2.75 85.05 90 top
NOREF#2  -  []  13.14 27.5 90 top
NOREF#3  -  []  183.61 57.58 90 top
NOREF#4  -  []  120.53 58.6 0 top
NOREF#5  -  []  186.68 137.11 180 top
NOREF#6  -  []  -11.91 21.69 90 top
NOREF#7  -  []  11.92 116.84 90 top
NOREF#8  -  []  30.2 102.8 0 top
NOREF#9  -  []  -1.8 127.92 0 top
NOREF#10  -  []  192.55 67.73 0 top
NOREF#11  -  []  4.01 10.35 0 top
NOREF#12  -  []  11.92 116.84 90 top
NOREF#13  -  []  116.29 109.22 90 top
NOREF#14  -  []  68.93 84.31 0 top
NOREF#15  -  []  3.41 19.9 0 top
NOREF#16  -  []  186.83 41.3 0 top
NOREF#17  -  []  3.41 19.9 90 top
NOREF#18  -  []  82.3 64.31 0 top
NOREF#19  -  []  5.44 23.15 90 top
NOREF#20  *  [unnamed#2]  5.57 150.03 0 top
NOREF#21  -  []  -0.25 67.47 90 top
NOREF#22  -  []  21.33 21.86 90 top
NOREF#23  -  []  -11.3 15.8 0 top
NOREF#24  -  []  51.4 96.63 90 top
NOREF#25  -  []  186.83 41.3 0 top
NOREF#26  -  []  12.24 24.6 90 top
NOREF#27  -  []  188 32.1 0 top
NOREF#28  -  []  3.41 15.2 0 top
NOREF#29  -  []  202.45 58.85 0 top
NOREF#30  -  []  -0.81 48.84 90 top
NOREF#31  -  []  83.04 83.86 90 top
NOREF#32  -  []  164.8 34.85 90 top
NOREF#33  -  []  194.95 58.85 0 top
NOREF#34  -  []  183.61 60.45 0 top
NOREF#35  -  []  148.34 28.49 90 top
NOREF#36  -  []  11.64 27 90 top
NOREF#37  -  []  173.71 34.91 0 top
NOREF#38  -  []  192.55 60.8 90 top
NOREF#39  -  []  12.85 80.22 0 top
NOREF#40  -  []  12.85 80.22 0 top
NOREF#41  -  []  53.29 105.98 0 top
NOREF#42  -  []  177.4 64.1 0 top
NOREF#43  -  []  116.83 153.31 0 top
NOREF#44  -  []  184.79 156.49 180 top
NOREF#45  -  []  5.44 23.15 90 top
NOREF#46  -  []  177.8 41.37 0 top
NOREF#47  -  []  186.83 40.3 90 top
NOREF#48  -  []  194.95 58.85 90 top
NOREF#49  -  []  159.16 28.49 90 top
NOREF#50  -  []  4.01 10.35 90 top
NOREF#51  -  []  -0.25 67.47 90 top
NOREF#52  -  []  159.83 39.54 0 top
NOREF#53  -  []  185.73 59.05 0 top
NOREF#54  -  []  152.9 27.48 90 top
NOREF#55  -  []  -1.48 39.31 0 top
NOREF#56  -  []  51.4 96.63 90 top
NOREF#57  -  []  4.01 10.35 0 top
NOREF#58  -  []  2.75 68.25 90 top
NOREF#59  -  []  207.7 58.08 90 top
NOREF#60  *  [unnamed#2]  174 153.24 0 top
NOREF#61  -  []  160.9 36.8 90 top
NOREF#62  -  []  -1.8 127.92 0 top
NOREF#63  -  []  68.93 84.96 90 top
NOREF#64  -  []  152.9 27.48 90 top
NOREF#65  -  []  184.52 39.93 90 top
NOREF#66  *  [unnamed#2]  221.22 150.03 0 top
NOREF#67  -  []  68.24 83.17 0 top
NOREF#68  -  []  -0.25 67.47 90 top
NOREF#69  -  []  11.64 51.65 90 top
NOREF#70  -  []  29 104.88 0 top
NOREF#71  -  []  152.9 33.5 90 top
NOREF#72  -  []  72.19 82.17 0 top
NOREF#73  *  [unnamed#2]  89.59 150.7 0 top
NOREF#74  -  []  68.93 84.96 90 top
NOREF#75  -  []  199.7 60.8 90 top
NOREF#76  -  []  51.4 96.63 90 top
NOREF#77  -  []  5.44 47.8 90 top
NOREF#78  -  []  116.29 159.31 0 top
NOREF#79  -  []  53.29 105.98 0 top
NOREF#80  -  []  199.7 60.8 90 top
NOREF#81  -  []  192.55 60.8 0 top
NOREF#82  -  []  1.44 82.45 0 top
NOREF#83  -  []  13.14 34.5 90 top
NOREF#84  -  []  -3.99 15.2 90 top
NOREF#85  -  []  192.55 60.8 0 top
NOREF#86  -  []  168.05 36.8 90 top
NOREF#87  -  []  116.26 6.63 0 top
NOREF#88  -  []  6 85.85 0 top
NOREF#89  -  []  5.44 47.8 90 top
NOREF#90  -  []  -0.25 79.55 0 top
NOREF#91  -  []  11.9 82.9 90 top
NOREF#92  -  []  11.64 35 90 top
NOREF#93  -  []  138.38 110.26 90 top
NOREF#94  -  []  -0.14 18.9 0 top
NOREF#95  -  []  68.24 83.17 0 top
NOREF#96  -  []  51.4 96.63 90 top
NOREF#97  -  []  176.15 39.28 90 top
NOREF#98  -  [unnamed#2]  228.54 147.42 0 top
NOREF#99  -  []  195.8 62.75 0 top
NOREF#100  -  []  199.7 60.8 90 top
NOREF#101  -  []  5.57 11.29 90 top
NOREF#102  -  []  138.38 109.76 90 top
NOREF#103  -  []  13.14 54.65 90 top
NOREF#104  -  []  156.15 38.75 0 top
NOREF#105  -  []  190.07 48.19 0 top
NOREF#106  -  []  30.89 105.98 0 top
NOREF#107  -  []  68.93 84.31 0 top
NOREF#108  -  []  157.49 28.49 90 top
NOREF#109  -  []  194.95 58.85 0 top
NOREF#110  -  [unnamed#2]  -0.21 151.42 0 top
NOREF#111  -  []  68.93 84.96 90 top
NOREF#112  -  []  11.92 116.84 90 top
NOREF#113  -  []  157 34.85 0 top
NOREF#114  -  []  2.72 116.92 0 top
NOREF#115  -  []  11.64 59.65 90 top
NOREF#116  -  []  190.07 44.05 90 top
NOREF#117  -  []  232.5 140.6 0 top
NOREF#118  -  []  219.61 129.44 90 top
NOREF#119  *  [unnamed#2]  8.51 2.41 0 top
NOREF#120  -  []  156.92 36.81 0 top
NOREF#121  -  []  70.62 2.03 0 top
NOREF#122  -  []  184.39 59.23 0 top
NOREF#123  -  []  153.75 36.8 0 top
NOREF#124  -  []  147.77 36.81 0 top
NOREF#125  -  []  191.7 64.1 0 top
NOREF#126  -  []  51.4 104.88 0 top
NOREF#127  -  []  83.04 83.86 90 top
NOREF#128  -  []  114.56 57.96 0 top
NOREF#129  -  []  148.34 28.49 90 top
NOREF#130  -  []  195.8 62.75 0 top
NOREF#131  -  []  192.55 60.8 90 top
NOREF#132  -  [unnamed#2]  56.11 4.87 0 top
NOREF#133  -  []  13.95 73.08 90 top
NOREF#134  -  []  5.28 22.36 0 top
NOREF#135  -  []  138.38 109.76 90 top
NOREF#136  -  []  -3.99 26.86 0 top
NOREF#137  -  []  2.72 116.92 0 top
NOREF#138  -  []  177.8 38.49 90 top
NOREF#139  -  []  -2.69 32.13 0 top
NOREF#140  -  []  3.41 15.2 90 top
NOREF#141  -  []  228.48 126.8 270 top
NOREF#142  -  []  135.87 60.58 0 top
NOREF#143  -  []  116.29 109.22 90 top
NOREF#144  -  []  30.2 102.8 0 top
NOREF#145  -  []  -11.3 15.8 0 top
NOREF#146  *  [unnamed#2]  227.46 31.42 0 top
NOREF#147  -  []  2.72 116.92 0 top
NOREF#148  -  []  182.43 38.28 0 top
NOREF#149  -  []  13.14 59.15 90 top
NOREF#150  *  [unnamed#2]  -1.74 4.41 0 top
NOREF#151  *  [unnamed#2]  40.64 4.41 0 top
NOREF#152  -  []  2.75 85.05 0 top
NOREF#153  -  []  168.31 28.49 90 top
NOREF#154  -  []  173.71 32.04 90 top
NOREF#155  -  []  -1.48 63.96 0 top
NOREF#156  -  []  3.41 19.9 90 top
NOREF#157  -  []  207.7 58.08 90 top
NOREF#158  -  []  -0.81 24.19 0 top
NOREF#159  -  []  172.06 32.82 90 top
NOREF#160  -  [unnamed#2]  3.7 7.3 0 top
NOREF#161  -  []  150.68 39.54 0 top
NOREF#162  -  [unnamed#2]  105.05 14.71 0 top
NOREF#163  -  []  -1.8 127.92 0 top
NOREF#164  -  []  183.39 50.73 0 top
NOREF#165  -  []  30.2 102.8 0 top
NOREF#166  -  []  178.25 67.73 0 top
NOREF#167  -  []  3.41 19.9 0 top
NOREF#168  -  []  153.75 37.13 0 top
NOREF#169  *  [unnamed#2]  157.05 111.08 0 top
NOREF#170  -  []  -0.25 67.47 90 top
NOREF#171  -  []  4.01 10.35 90 top
NOREF#172  -  []  148.34 38.65 0 top
NOREF#173  -  []  -0.81 24.19 90 top
NOREF#174  -  []  -2.69 56.78 0 top
NOREF#175  -  []  3.41 15.2 0 top
NOREF#176  -  []  177.4 58.08 90 top
NOREF#177  -  []  51.4 96.63 90 top
NOREF#178  -  []  51.4 96.63 90 top
NOREF#179  -  []  199.7 60.8 90 top
NOREF#180  -  [unnamed#2]  -3.21 43.23 0 top
NOREF#181  -  []  116.29 159.31 0 top
NOREF#182  -  []  138.38 110.26 90 top
NOREF#183  -  []  -3.99 26.86 0 top
NOREF#184  -  []  -2.06 85.96 0 top
NOREF#185  -  []  12.24 49.25 90 top
NOREF#186  -  []  188 32.1 90 top
NOREF#187  -  []  122.28 158.76 0 top
NOREF#188  -  []  12.24 37.4 90 top
NOREF#189  -  []  184.52 42.8 0 top
NOREF#190  -  []  116.83 153.31 0 top
NOREF#191  -  [unnamed#2]  58.2 141.2 0 top
NOREF#192  -  []  116.83 115.21 90 top
NOREF#193  -  []  122.28 158.76 0 top
NOREF#194  -  []  5.28 47.01 0 top
NOREF#195  -  []  186.83 41.3 0 top
NOREF#196  -  []  19.08 54.31 90 top
NOREF#197  -  []  -2.1 11.29 0 top
NOREF#198  -  []  152.9 33.5 0 top
NOREF#199  -  []  116.83 115.21 90 top
NOREF#200  -  []  51.4 96.63 90 top
NOREF#201  -  []  157.65 38.75 0 top
NOREF#202  -  []  194.95 58.85 90 top
NOREF#203  -  []  11.64 27 90 top
NOREF#204  -  []  51.4 96.63 90 top
NOREF#205  -  []  51.4 104.88 0 top
NOREF#206  -  []  13.14 52.15 90 top
NOREF#207  -  []  3.41 19.9 0 top
NOREF#208  -  []  12.85 80.22 90 top
NOREF#209  -  []  -7.69 18.9 0 top
NOREF#210  -  []  51.4 96.63 90 top
NOREF#211  -  []  177.4 58.08 90 top
NOREF#212  -  []  21.33 46.51 90 top
NOREF#213  -  []  83.04 83.86 90 top
NOREF#214  -  []  4.85 86.35 90 top
NOREF#215  -  []  -0.81 48.84 0 top
NOREF#216  -  []  168.31 28.49 90 top
NOREF#217  -  []  11.64 51.65 90 top
NOREF#218  -  [unnamed#2]  196.4 71.76 0 top
NOREF#219  -  []  72.19 82.17 0 top
NOREF#220  -  []  3.7 7.3 0 top
NOREF#221  -  []  13.14 30 90 top
NOREF#222  -  []  19.08 29.66 90 top
NOREF#223  -  []  3.41 15.2 0 top
NOREF#224  -  []  189.17 33.8 90 top
NOREF#225  -  []  157.49 38.65 0 top
NOREF#226  -  []  12.24 62.05 90 top
NOREF#227  -  []  202.45 58.85 0 top
NOREF#228  *  [unnamed#2]  40.64 4.41 180 bottom
NOREF#229  -  []  153.29 55.17 180 bottom
NOREF#230  *  [unnamed#2]  125.76 79.53 180 bottom
NOREF#231  *  [unnamed#2]  221.22 150.03 180 bottom
NOREF#232  *  [unnamed#2]  145.52 122.15 180 bottom
NOREF#233  *  [unnamed#2]  227.46 31.42 180 bottom
NOREF#234  *  [unnamed#2]  174 153.24 180 bottom
NOREF#235  -  []  228.48 109.91 90 bottom
NOREF#236  *  [unnamed#2]  5.57 150.03 180 bottom
NOREF#237  *  [unnamed#2]  102.49 118.87 180 bottom
NOREF#238  *  [unnamed#2]  151.01 152.2 180 bottom
NOREF#239  *  [unnamed#2]  -1.74 4.41 180 bottom
NOREF#240  *  [unnamed#2]  49.2 89.33 180 bottom
ODD1  ACES-CONN16D-5-GP  [50552-01601-001]  188 37.55 270 bottom
PC1001  SC22U6D3V3MX-1-DL-GP  [C603H40]  63.36 120.1 270 top
PC1002  SC22U6D3V3MX-1-DL-GP  [C603H40]  86.59 121.33 90 top
PC1003  SC22U6D3V3MX-1-DL-GP  [C603H40]  86.59 122.5 90 top
PC1004  SC22U6D3V3MX-1-DL-GP  [C603H40]  86.59 123.67 90 top
PC1005  SC22U6D3V3MX-1-DL-GP  [C603H40]  88.51 117.79 90 top
PC1006  SC22U6D3V3MX-1-DL-GP  [C603H40]  86.59 118.99 90 top
PC1007  SC22U6D3V3MX-1-DL-GP  [C603H40]  94.07 93.14 90 top
PC1008  SC22U6D3V3MX-1-DL-GP  [C603H40]  88.51 115.45 90 top
PC1009  SC22U6D3V3MX-1-DL-GP  [C603H40]  77.48 120.05 270 top
PC1010  SC22U6D3V3MX-1-DL-GP  [C603H40]  77.48 118.88 270 top
PC1011  SC22U6D3V3MX-1-DL-GP  [C603H40]  77.48 117.71 270 top
PC1012  SC22U6D3V3MX-1-DL-GP  [C603H40]  86.59 124.83 90 top
PC1013  SC22U6D3V3MX-1-DL-GP  [C603H40]  94.07 96.65 90 top
PC1014  SC22U6D3V3MX-1-DL-GP  [C603H40]  94.9 91.26 180 top
PC1015  SC22U6D3V3MX-1-DL-GP  [C603H40]  94.07 94.31 90 top
PC1016  SC22U6D3V3MX-1-DL-GP  [C603H40]  77.48 115.38 270 top
PC1017  SC22U6D3V3MX-1-DL-GP  [C603H40]  86.6 126.04 90 top
PC1018  SC22U6D3V3MX-1-DL-GP  [C603H40]  92.03 90.81 270 top
PC1019  SC22U6D3V3MX-1-DL-GP  [C603H40]  86.59 120.16 90 top
PC1020  SC22U6D3V3MX-1-DL-GP  [C603H40]  87.93 95.56 90 top
PC1021  SC22U6D3V3MX-1-DL-GP  [C603H40]  87.93 97.89 90 top
PC1022  SC22U6D3V3MX-1-DL-GP  [C603H40]  91 97.89 270 top
PC1023  SC22U6D3V3MX-1-DL-GP  [C603H40]  91 96.72 270 top
PC1024  SC22U6D3V3MX-1-DL-GP  [C603H40]  91 95.56 270 top
PC1025  SC22U6D3V3MX-1-DL-GP  [C603H40]  91 94.39 270 top
PC1026  SC22U6D3V3MX-1-DL-GP  [C603H40]  91 93.22 270 top
PC1027  SC22U6D3V3MX-1-DL-GP  [C603H40]  87.93 99.06 90 top
PC1028  SC22U6D3V3MX-1-DL-GP  [C603H40]  77.48 116.54 270 top
PC1029  SC22U6D3V3MX-1-DL-GP  [C603H40]  77.48 121.22 270 top
PC1030  SC22U6D3V3MX-1-DL-GP  [C603H40]  88.51 116.62 90 top
PC1031  SC22U6D3V3MX-1-DL-GP  [C603H40]  87.93 94.39 90 top
PC1032  SC22U6D3V3MX-1-DL-GP  [C603H40]  84.37 94.69 270 top
PC1034  SC22U6D3V3MX-1-DL-GP  [C603H40]  84.37 93.5 270 top
PC1036  SC22U6D3V3MX-1-DL-GP  [C603H40]  94.07 97.82 90 top
PC1037  SC22U6D3V3MX-1-DL-GP  [C603H40]  65.76 96.98 270 top
PC1038  SC22U6D3V3MX-1-DL-GP  [C603H40]  81.82 96.04 180 top
PC1039  SC22U6D3V3MX-1-DL-GP  [C603H40]  77.12 96.03 180 top
PC1040  SC22U6D3V3MX-1-DL-GP  [C603H40]  75.85 99.16 0 top
PC1041  SC22U6D3V3MX-1-DL-GP  [C603H40]  74.68 99.16 0 top
PC1042  SC22U6D3V3MX-1-DL-GP  [C603H40]  78.19 99.16 0 top
PC1043  SC22U6D3V3MX-1-DL-GP  [C603H40]  74.7 96.04 180 top
PC1044  SC22U6D3V3MX-1-DL-GP  [C603H40]  63.38 124.79 270 top
PC1045  SC22U6D3V3MX-1-DL-GP  [C603H40]  63.38 123.62 270 top
PC1046  SC22U6D3V3MX-1-DL-GP  [C603H40]  79.48 96.03 180 top
PC1047  SC22U6D3V3MX-1-DL-GP  [C603H40]  75.92 96.03 180 top
PC1048  SC22U6D3V3MX-1-DL-GP  [C603H40]  65.76 99.32 270 top
PC1049  SC22U6D3V3MX-1-DL-GP  [C603H40]  63.36 115.42 270 top
PC1050  SC22U6D3V3MX-1-DL-GP  [C603H40]  63.36 121.27 270 top
PC1051  SC22U6D3V3MX-1-DL-GP  [C603H40]  74.84 117.73 90 top
PC1052  SC22U6D3V3MX-1-DL-GP  [C603H40]  63.36 122.43 270 top
PC1053  SC22U6D3V3MX-1-DL-GP  [C603H40]  81.74 92.1 0 top
PC1054  SC22U6D3V3MX-1-DL-GP  [C603H40]  78.29 96.03 180 top
PC1055  SC22U6D3V3MX-1-DL-GP  [C603H40]  65.76 98.15 270 top
PC1056  SC22U6D3V3MX-1-DL-GP  [C603H40]  63.36 116.59 270 top
PC1057  SC22U6D3V3MX-1-DL-GP  [C603H40]  63.36 118.93 270 top
PC1058  SC22U6D3V3MX-1-DL-GP  [C603H40]  80.65 96.04 180 top
PC1059  SC22U6D3V3MX-1-DL-GP  [C603H40]  75.67 92.08 0 top
PC1060  SC22U6D3V3MX-1-DL-GP  [C603H40]  76.86 92.08 0 top
PC1061  SC22U6D3V3MX-1-DL-GP  [C603H40]  69.93 115.37 90 top
PC1062  SC22U6D3V3MX-1-DL-GP  [C603H40]  63.36 117.76 270 top
PC1063  SC22U6D3V3MX-1-DL-GP  [C603H40]  65.76 95.8 270 top
PC1064  SC22U6D3V3MX-1-DL-GP  [C603H40]  74.84 115.37 90 top
PC1065  SC22U6D3V3MX-1-DL-GP  [C603H40]  78.05 92.08 0 top
PC1066  SC22U6D3V3MX-1-DL-GP  [C603H40]  80.53 92.09 0 top
PC1067  SC22U6D3V3MX-1-DL-GP  [C603H40]  74.84 116.54 90 top
PC1068  SC22U6D3V3MX-1-DL-GP  [C603H40]  79.28 92.08 0 top
PC1069  SC22U6D3V3MX-1-DL-GP  [C603H40]  69.93 116.54 90 top
PC1070  SC22U6D3V3MX-1-DL-GP  [C603H40]  77.02 99.16 0 top
PC1071  SC22U6D3V3MX-1-DL-GP  [C603H40]  97.16 95.51 270 top
PC1072  SC22U6D3V3MX-1-DL-GP  [C603H40]  97.16 93.17 270 top
PC1073  SC22U6D3V3MX-1-DL-GP  [C603H40]  97.16 96.67 270 top
PC1074  SC22U6D3V3MX-1-DL-GP  [C603H40]  97.16 97.84 270 top
PC1075  SC22U6D3V3MX-1-DL-GP  [C603H40]  97.16 99.01 270 top
PC1076  SC22U6D3V3MX-1-DL-GP  [C603H40]  97.16 94.34 270 top
PC1077  SC22U6D3V3MX-1-DL-GP  [C603H40]  89.87 122.1 270 top
PC1078  SC22U6D3V3MX-1-DL-GP  [C603H40]  89.87 123.39 270 top
PC1079  SC22U6D3V3MX-1-DL-GP  [C603H40]  94.07 98.99 90 top
PC1080  SC22U6D3V3MX-1-DL-GP  [C603H40]  87.93 96.72 90 top
PC1081  SC22U6D3V3MX-1-DL-GP  [C603H40]  87.93 93.22 90 top
PC1082  SC22U6D3V3MX-1-DL-GP  [C603H40]  84.37 95.89 270 top
PC1083  SC22U6D3V3MX-1-DL-GP  [C603H40]  91 99.06 270 top
PC1084  SC22U6D3V3MX-1-DL-GP  [C603H40]  94.07 95.48 90 top
PC4402  SC10U25V5KX-DL-GP  [C805H58]  187.61 56.54 180 bottom
PC4403  SC10U25V5KX-DL-GP  [C805H58]  193.94 56.33 270 bottom
PC4404  SC10U25V5KX-DL-GP  [C805H58]  189.26 60.66 0 bottom
PC4405  SC10U25V5KX-DL-GP  [C805H58]  189.33 56.54 180 bottom
PC4406  SCD1U25V2KX-1-DL-GP  [C402H22]  181.77 33.99 90 top
PC4407  SC10U25V3MX-3-GP  [C603H40]  183.87 35.26 270 bottom
PC4408  SC10U25V3MX-3-GP  [C603H40]  183.21 32.31 180 bottom
PC4409  SC10U25V3MX-3-GP  [C603H40]  179.63 59.34 90 bottom
PC4410  SC10U25V3MX-3-GP  [C603H40]  177.9 35.97 90 bottom
PC4411  SC10U25V3MX-3-GP  [C603H40]  183.87 34.08 270 bottom
PC4412  SC10U25V3MX-3-GP  [C603H40]  179.63 58.17 90 bottom
PC4413  SC10U25V5KX-DL-GP  [C805H58]  180.14 68.1 0 bottom
PC4414  SC10U25V3MX-3-GP  [C603H40]  182.04 32.31 180 bottom
PC4415  SC4D7U25V3KX-GP  [C603H40]  204.27 53.29 270 bottom
PC4416  SC1U25V3KX-1-DLGP  [C603H36]  204.83 54.74 90 bottom
PC4417  SC1U25V3KX-1-DLGP  [C603H36]  202.45 54.74 270 bottom
PC4418  SC10U25V5KX-DL-GP  [C805H58]  182.15 61.01 315 bottom
PC4419  SC1U25V3KX-1-DLGP  [C603H36]  207.47 51.2 270 bottom
PC4420  SCD022U16V2KX-3DLGP  [C402H22]  204.42 51.03 180 top
PC4421  SC4D7U6D3V3KX-DLGP  [C603H36]  198 52.18 90 bottom
PC4422  SC4D7U6D3V3KX-DLGP  [C603H36]  207.47 50.03 270 bottom
PC4423  SCD22U25V3KX-DL-GP  [C603H36]  197.92 48.21 90 bottom
PC4424  SC1U25V3KX-1-DLGP  [C603H36]  196.13 46.76 180 bottom
PC4425  SC1U25V3KX-1-DLGP  [C603H36]  197.4 45.24 180 bottom
PC4426  SC1U25V3KX-1-DLGP  [C603H36]  196.13 44.38 0 bottom
PC4427  SC10U25V5KX-DL-GP  [C805H58]  178.82 32.46 180 bottom
PC4429  SC4700P50V2KX-1DLGP  [C402H22]  176.71 34.67 270 top
PC4430  SC10P50V2JN-4DLGP  [C402H22]  205.21 47.22 270 top
PC4431  SCD01U25V2KX-3DLGP  [C402H22]  194.69 44.76 0 top
PC4432  SC1KP50V2KX-1DLGP  [C402H22]  202.93 43.42 270 bottom
PC4433  SC470P50V2KX-3DLGP  [C402H22]  195.81 44.25 270 top
PC4434  SC10U25V5KX-DL-GP  [C805H58]  179.96 64.8 180 bottom
PC4435  SC1KP50V2KX-1DLGP  [C402H22]  195.89 50.83 180 top
PC4436  SCD22U25V3KX-DL-GP  [C603H36]  199.47 54.79 0 bottom
PC4437  SC10U25V5KX-DL-GP  [C805H58]  180.9 62.23 315 bottom
PC4438  SCD1U16V2KX-3DLGP  [C402H22]  205.31 41.48 180 top
PC4439  SC1U25V3KX-1-DLGP  [C603H36]  197.92 47.02 270 bottom
PC4440  SC1U25V3KX-1-DLGP  [C603H36]  201.58 44.44 0 bottom
PC4441  SC2200P50V2KX-2DLGP  [C402H22]  204.07 47.16 180 top
PC4442  SC1KP50V2KX-1DLGP  [C402H22]  198.22 50.85 0 bottom
PC4443  SC2200P50V2KX-2GP  [C402H22]  178.36 36.22 270 top
PC4445  SC1KP50V2KX-1DLGP  [C402H22]  200.72 46.03 90 bottom
PC4446  SC10U25V5KX-DL-GP  [C805H58]  147.07 39.8 0 bottom
PC4447  SC10U25V5KX-DL-GP  [C805H58]  148.8 39.8 0 bottom
PC4448  SC10U25V5KX-DL-GP  [C805H58]  180.55 32.46 180 bottom
PC4449  SCD1U16V2KX-3DLGP  [C402H22]  14.23 123.5 180 bottom
PC4501  SCD1U25V2KX-GP  [C402H22]  57.81 137.09 270 bottom
PC4502  SC10U25V5KX-DL-GP  [C805H58]  56.04 132.41 180 bottom
PC4503  SC10U25V5KX-DL-GP  [C805H58]  57.33 135.84 270 bottom
PC4504  SC10U25V5KX-DL-GP  [C805H58]  54.31 132.41 180 bottom
PC4505  SC10U25V5KX-GP  [C805H56]  48.21 32.08 180 bottom
PC4506  SCD1U25V2KX-GP  [C402H22]  61.2 131.38 0 top
PC4507  SC4D7U6D3V3KX-GP  [C603H36]  62.57 130.97 270 bottom
PC4508  SCD1U25V2KX-GP  [C402H22]  60.68 135.21 270 top
PC4509  SC22U6D3V3MX-1-DL-GP  [C603H40]  52.81 124.82 180 bottom
PC4510  SC22U6D3V3MX-1-DL-GP  [C603H40]  55.12 130.58 180 top
PC4511  SC22U6D3V3MX-1-DL-GP  [C603H40]  57.15 125.26 0 top
PC4512  SC22U6D3V3MX-1-DL-GP  [C603H40]  55.85 125.26 0 top
PC4513  SCD1U25V2KX-1-DL-GP  [C402H22]  54.14 130.27 180 top
PC4514  SC22U6D3V3MX-1-DL-GP  [C603H40]  53.22 40.13 0 bottom
PC4515  SC22U6D3V3MX-1-DL-GP  [C603H40]  53.22 36.88 180 bottom
PC4516  SC22U6D3V3MX-1-DL-GP  [C603H40]  54.38 37.26 180 bottom
PC4517  SC22U6D3V3MX-1-DL-GP  [C603H40]  52.05 40.13 0 bottom
PC4518  SCD1U16V2KX-3GP  [C402H22]  55.35 36.83 180 bottom
PC4519  SC10U25V5KX-GP  [C805H56]  49.96 32.07 180 bottom
PC4520  SC4D7U6D3V3KX-DLGP  [C603H36]  41.36 39.8 0 bottom
